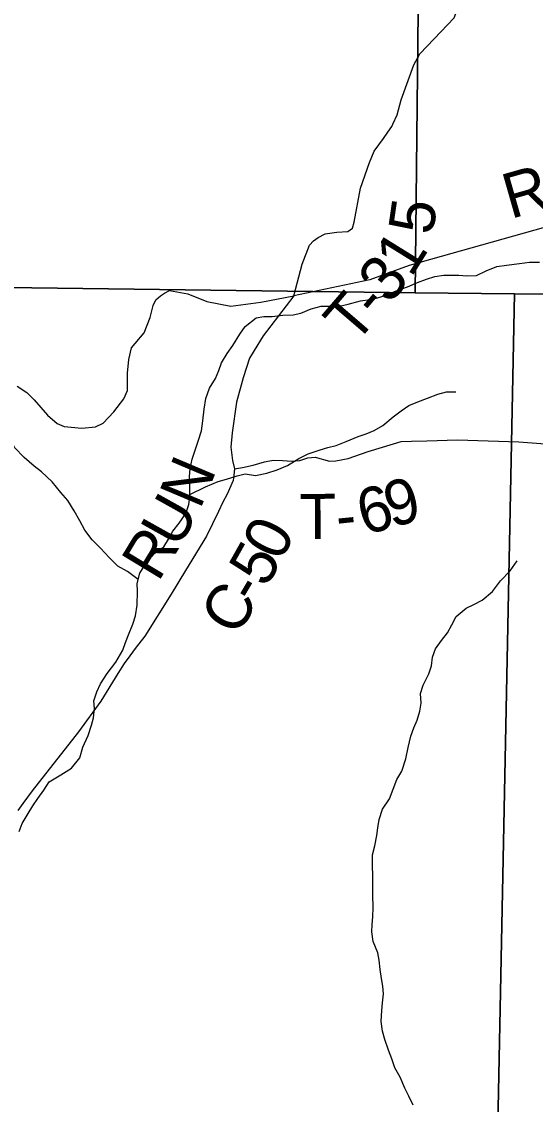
# Model space of a CAD drawing. Extents: x 2043100 to 2470832, y 443715 to 810583.
# Drawn here: x 2261128 to 2264540, y 633122 to 640318 of the extents above; entities that cross this region are included whole.
import ezdxf

# ---------------------------------------------------------------- set-up
doc = ezdxf.new("R2010")
doc.units = 0
for name, color, linetype in [('GM_X_County_Road', 7, 'Continuous'), ('GM_X_County_Road_Text', 7, 'Continuous'), ('GM_X_Minor_River', 7, 'Continuous'), ('GM_X_Section', 7, 'Continuous'), ('GM_X_Township_Road', 7, 'Continuous'), ('GM_X_Township_Road_Text', 7, 'Continuous'), ('GM_X_Township_ROW', 7, 'Continuous')]:
    doc.layers.add(name, color=color, linetype=linetype)

msp = doc.modelspace()

# ---------------------------------------------------------------- linework, layer by layer
at = {"layer": 'GM_X_County_Road'}
for points in [[(2265158.5, 639107), (2263701.9, 638697.1), (2263440.6, 638602.6), (2262936, 638495)], [(2261098.5, 637895.4), (2261160.9, 637853.8), (2261211.4, 637804.1), (2261298.2, 637702.5), (2261362.7, 637646.9), (2261410.9, 637627.2), (2261527.2, 637616.1), (2261619.2, 637624.9), (2261669.1, 637649.3), (2261740.6, 637724), (2261806, 637810.7), (2261831.6, 637867), (2261830.7, 637981.3), (2261840.1, 638071.6), (2261857.5, 638149.9), (2261940.5, 638249.5), (2261981.4, 638351), (2262001.5, 638431.6), (2262019.3, 638467.8), (2262049.1, 638496.1), (2262077, 638512.4), (2262110.2, 638529.8), (2262231.4, 638508.6), (2262358.7, 638457.1), (2262517, 638427.1), (2262716.1, 638453.2), (2262936, 638495)], [(2262936, 638495), (2262732.2, 638229.7), (2262671.4, 638132.6), (2262642, 638082.1), (2262599.7, 637951.2), (2262555.7, 637788.2), (2262526.4, 637585.3), (2262517.6, 637488.9), (2262528.8, 637400.8), (2262541.5, 637344.9), (2262538.1, 637302.7), (2262532.5, 637268.5), (2262493.7, 637177.8), (2262464.3, 637123.2), (2262435.1, 637062.7), (2262355.1, 636897.2), (2262215.9, 636670.7), (2262121.8, 636513.1), (2261945.2, 636233.9), (2261882.2, 636150.9), (2261846.8, 636102.3), (2261809.4, 636051.6), (2261766.2, 635984.9), (2261654.5, 635800.9), (2261504.9, 635598.4), (2261197.6, 635205.2), (2261134.6, 635122.1), (2261103.1, 635075.6)]]:
    msp.add_lwpolyline(points, dxfattribs=at)
at = {"layer": 'GM_X_Minor_River'}
for points in [[(2263296.4, 638440.6), (2263378.5, 638463), (2263442.6, 638471.3), (2263492.7, 638481.6), (2263548.8, 638499.8), (2263616.8, 638528.2), (2263690.9, 638554.5), (2263756.9, 638584.9), (2263817, 638607.2), (2263873, 638623.4), (2263933.2, 638631.7), (2264031.4, 638632.1), (2264085.6, 638628.4), (2264149.7, 638630.7), (2264213.7, 638661), (2264283.8, 638689.3), (2264347.9, 638699.7), (2264434.1, 638710), (2264502.2, 638718.4), (2264568.4, 638718.7)], [(2261110.2, 634934.4), (2261130, 634988.6), (2261169.8, 635054.8), (2261201.7, 635105), (2261235.6, 635155.3), (2261275.4, 635209.5), (2261309.3, 635265.7), (2261387.3, 635312.1), (2261459.2, 635356.5), (2261513.1, 635424.8), (2261534.8, 635495), (2261568.6, 635573.3), (2261592.3, 635641.5), (2261604.1, 635691.6), (2261611.9, 635753.7), (2261607.7, 635803.8), (2261627.4, 635863.9), (2261651.3, 635916.1), (2261695.1, 635984.4), (2261752.9, 636060.7), (2261800.7, 636141), (2261816.5, 636191.2), (2261838.3, 636243.3), (2261866.1, 636313.5), (2261883.9, 636367.7), (2261895.6, 636439.8), (2261897.2, 636532), (2261895, 636584), (2261912.7, 636652.2), (2261958.5, 636728.5), (2262012.4, 636784.8), (2262072.4, 636827.1), (2262102.2, 636877.3), (2262132, 636931.5), (2262173.9, 636983.8), (2262217.8, 637048), (2262237.5, 637108.2), (2262245.3, 637160.3), (2262245.1, 637212.4), (2262242.7, 637292.5), (2262246.5, 637348.6), (2262260.3, 637410.7), (2262280.1, 637468.9), (2262299.9, 637529), (2262321.6, 637597.2), (2262331.3, 637665.4), (2262341, 637741.5), (2262350.7, 637813.6), (2262376.5, 637881.8), (2262416.3, 637946.1), (2262438.2, 637998.3), (2262456, 638050.4), (2262493.8, 638112.7), (2262529.7, 638164.9), (2262577.4, 638241.2), (2262613.3, 638291.4), (2262685.2, 638349.8), (2262737.3, 638358), (2262791.5, 638358.3), (2262863.6, 638366.6), (2262931.8, 638368.9), (2262981.9, 638379.2), (2263051.9, 638409.5), (2263118, 638425.8), (2263240.3, 638426.4), (2263296.4, 638440.6)], [(2262245.3, 637174.3), (2262349.3, 637224.9), (2262433.4, 637261.3), (2262487.4, 637277.5), (2262559.5, 637299.9), (2262611.6, 637312.1), (2262681.8, 637300.4), (2262755.9, 637316.8), (2262824, 637339.1), (2262894.1, 637367.4), (2262968.1, 637413.8), (2263032.1, 637444.2), (2263110.2, 637472.5), (2263162.2, 637486.8), (2263216.3, 637501), (2263284.4, 637527.4), (2263362.4, 637559.8), (2263416.5, 637578), (2263470.5, 637600.3), (2263526.5, 637632.6), (2263596.4, 637691), (2263648.4, 637731.3), (2263700.4, 637765.5), (2263760.4, 637791.8), (2263824.5, 637816.2), (2263892.5, 637842.5), (2263950.6, 637856.8), (2264012.8, 637857.1)], [(2261901.8, 636610.2), (2261830.5, 636663.8), (2261766.1, 636697.6), (2261709.7, 636757.4), (2261651.3, 636819.3), (2261594.9, 636873.1), (2261546.5, 636936.9), (2261514.2, 637000.9), (2261475.8, 637066.8), (2261435.4, 637134.7), (2261387, 637188.6), (2261330.6, 637258.4), (2261260.1, 637326.2), (2261209.8, 637364), (2261143.4, 637421.8), (2261081, 637487.6), (2261054.7, 637541.6), (2261034.4, 637593.6), (2260998, 637659.5)], [(2263728.8, 633117.6), (2263700.5, 633175.5), (2263672.2, 633229.5), (2263641.8, 633303.4), (2263607.4, 633365.4), (2263587.1, 633425.4), (2263564.8, 633481.3), (2263540.4, 633553.3), (2263524.1, 633607.3), (2263515.8, 633673.4), (2263519.5, 633745.5), (2263525.3, 633797.6), (2263531.1, 633855.7), (2263526.8, 633907.7), (2263518.6, 633957.8), (2263510.3, 634017.8), (2263502, 634079.8), (2263493.8, 634129.9), (2263463.4, 634203.8), (2263455.1, 634267.9), (2263456.8, 634317.9), (2263460.6, 634368), (2263462.4, 634430.1), (2263460, 634512.2), (2263461.7, 634572.3), (2263461.5, 634638.4), (2263459.1, 634710.5), (2263458.8, 634780.6), (2263474.6, 634840.7), (2263488.3, 634908.9), (2263494.1, 634958.9), (2263501.9, 635015.1), (2263525.7, 635083.3), (2263571.5, 635151.5), (2263595.3, 635215.7), (2263621, 635281.9), (2263652.9, 635336.2), (2263680.6, 635418.4), (2263696.3, 635492.5), (2263714, 635568.7), (2263733.8, 635624.9), (2263755.7, 635675.1), (2263773.4, 635735.2), (2263781.2, 635787.3), (2263776.9, 635851.4), (2263794.7, 635907.5), (2263832.5, 635983.8), (2263850.3, 636035.9), (2263858.1, 636094.1), (2263877.9, 636148.2), (2263917.7, 636204.5), (2263957.6, 636254.7), (2263985.5, 636308.9), (2264015.3, 636363.1), (2264081.2, 636419.5), (2264131.2, 636443.7), (2264187.3, 636472), (2264255.2, 636530.4), (2264309, 636600.7), (2264372.9, 636667.1), (2264420.7, 636733.4)]]:
    msp.add_lwpolyline(points, dxfattribs=at)
at = {"layer": 'GM_X_Section'}
for points in [[(2263800.1, 643920.5), (2263741.3, 638515.9), (2258136.1, 638587.9), (2258237.7, 643923)], [(2263800.1, 643920.5), (2269209.3, 643840), (2269174.3, 638453.9), (2264401.7, 638507.7), (2263741.3, 638515.9)], [(2258136.1, 638587.9), (2263741.3, 638515.9), (2264401.7, 638507.7), (2264289.9, 632876), (2258045.4, 632868.5), (2258053.6, 633190.7)], [(2264401.7, 638507.7), (2269174.3, 638453.9), (2269724.6, 638450.3), (2269681.7, 632921.5), (2264289.9, 632876)]]:
    msp.add_lwpolyline(points, close=True, dxfattribs=at)
at = {"layer": 'GM_X_Township_Road'}
for points in [[(2263593.2, 639636.1), (2263622, 639698.7), (2263648, 639798.9), (2263732, 640031.4), (2263772, 640103.5), (2263868.1, 640203.7), (2264000.2, 640342.1), (2264022.2, 640400.2), (2264014.1, 640436.2), (2264006.2, 640450.5), (2263979.5, 640498.6)], [(2262936, 638495), (2262990.6, 638705.6), (2263039, 638832.9), (2263066.3, 638861.7), (2263096.6, 638882.9), (2263143.6, 638907.1), (2263220.7, 638918.7), (2263293.6, 638922.3), (2263325.4, 638945), (2263336, 638984.4), (2263378.4, 639211.8), (2263438.6, 639382.4), (2263469.9, 639456.2), (2263532, 639540.3), (2263560.4, 639582.6), (2263586, 639620.5), (2263593.2, 639636.1)], [(2262541.5, 637344.9), (2262595.5, 637353.6), (2262665.4, 637370.6), (2262741.3, 637391.7), (2262799.2, 637402.5), (2262861.3, 637401.3), (2262923.5, 637396.2), (2262975.5, 637400.9), (2263029.4, 637417.7), (2263077.4, 637422.3), (2263171.9, 637397.5), (2263215.9, 637398.2), (2263295.8, 637413.3), (2263429.4, 637461.2), (2263525.2, 637490.6), (2263648.9, 637526.4), (2263717.5, 637528.4), (2263820.2, 637531.5)]]:
    msp.add_lwpolyline(points, dxfattribs=at)
at = {"layer": 'GM_X_Township_ROW'}
msp.add_lwpolyline([(2263820.2, 637531.5), (2264023.4, 637537.5), (2264430.2, 637525), (2264751, 637500.1), (2264817.6, 637494.9)], dxfattribs=at)

# ---------------------------------------------------------------- texts
at = {"layer": 'GM_X_County_Road_Text'}
for s, rotation, p in [('RD', 15.94436, (2264375.6, 639005)), ('N', 67.1035, (2262312.2, 637070)), ('U', 60.78452, (2262167.7, 636807.7)), ('0', 63.28861, (2262849.2, 636722.3)), ('R', 58.81335, (2262034.6, 636587.3)), ('5', 60.70216, (2262751.8, 636548)), ('-', 59.33448, (2262685.1, 636435.3)), ('C', 58.74305, (2262555.5, 636221.8))]:
    msp.add_text(s, height=300, rotation=rotation, dxfattribs=at).set_placement(p)
at = {"layer": 'GM_X_Township_Road_Text'}
for s, rotation, p in [('5', 81.87825, (2263858.5, 638894.1)), ('1', 58.17778, (2263715.2, 638610.8)), ('3', 50.31783, (2263571, 638432.2)), ('T', 49.32526, (2263341, 638164)), ('-', 49.49327, (2263487.9, 638334.9)), ('6', 15.10005, (2263403.3, 636903.4)), ('9', 15.70554, (2263585.1, 636952.5)), ('T', 0.34714, (2262973.1, 636878.4)), ('-', 5.75723, (2263228.3, 636881.4))]:
    msp.add_text(s, height=300, rotation=rotation, dxfattribs=at).set_placement(p)

doc.saveas('drawing.dxf')
